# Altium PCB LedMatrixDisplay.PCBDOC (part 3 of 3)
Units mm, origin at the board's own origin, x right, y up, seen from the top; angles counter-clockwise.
Board outline 305.05 x 54.1 mm, 4 copper layers (Top Layer, POWER, GROUND, Bottom Layer); 103 components, 165 nets, 805 pads, 317 vias.
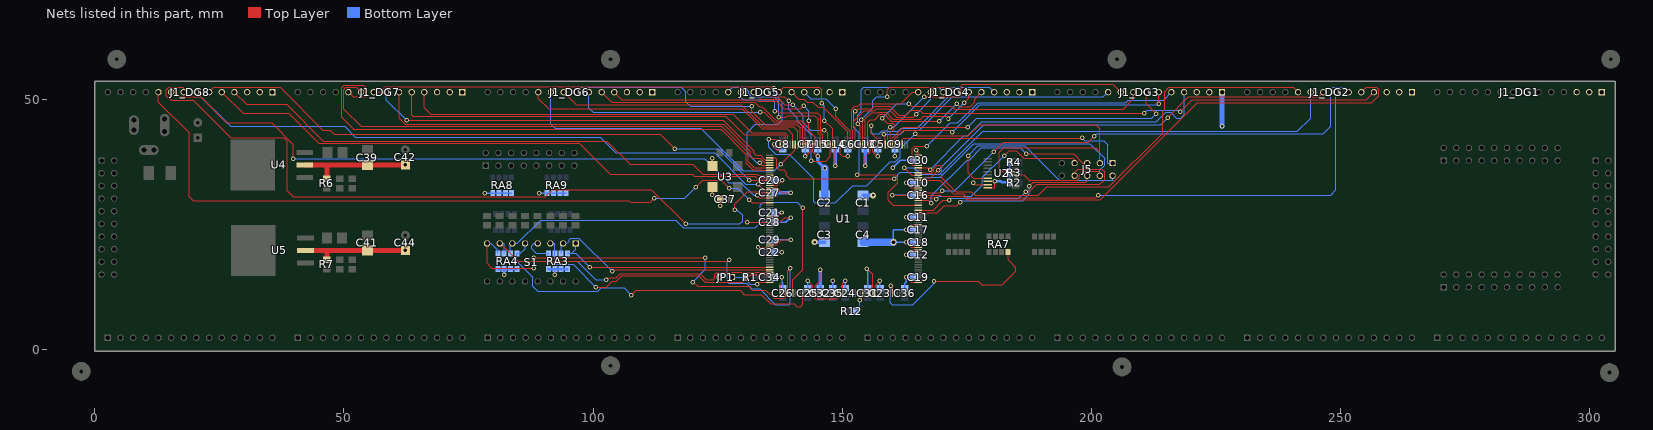
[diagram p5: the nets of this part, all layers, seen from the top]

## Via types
v1: diameter 0.9, hole 0.5, Top Layer to Bottom Layer, 307 vias
v2: diameter 1.2, hole 0.5, Top Layer to Bottom Layer, 9 vias
v3: diameter 1.27, hole 0.711, Top Layer to Bottom Layer, 1 vias

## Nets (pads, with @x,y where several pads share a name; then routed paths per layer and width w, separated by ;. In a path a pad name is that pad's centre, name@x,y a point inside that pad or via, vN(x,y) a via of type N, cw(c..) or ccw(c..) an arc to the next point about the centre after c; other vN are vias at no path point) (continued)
ROWB0: J1_DG2.4 U1.136 | length 141.5
  Top Layer w0.2: v1(152.629,47.752) 153.162,48.285 156.058,48.285 156.464,48.692 159.563,48.692 161.29,46.965 162.879,46.965 163.806,47.892 165.558,47.892 166.104,47.346 v1(210.566,47.346) ; v1(153.035,35.001) 160.757,35.001 161.163,34.595 161.163,33.35 159.258,31.445 159.258,29.863 160.198,28.923 U1.136@165.227,28.923 ; v1(217.805,47.6) 220.218,50.013 255.118,50.013 J1_DG2.4@256.667,51.562
  Bottom Layer w0.2: v1(152.629,47.752) 152.324,47.447 152.324,44.475 153.442,43.358 153.442,35.408 v1(153.035,35.001) ; v1(210.566,47.346) 211.201,47.981 217.424,47.981 v1(217.805,47.6)
ROWB1: J1_DG2.5 U1.140 | length 106.7
  Top Layer w0.2: U1.140@165.227,30.923 169.647,30.923 169.913,30.658 174.244,30.658 174.956,29.947 201.753,29.947 221.26,49.454 256.21,49.454 257.607,50.851 257.607,52.07 257.15,52.527 255.093,52.527 J1_DG2.5@254.127,51.562
ROWB2: J1_DG2.6 U1.141 | length 99.8
  Top Layer w0.2: U1.141@165.227,31.423 169.625,31.423 v1(170.028,31.826) ; v1(180.366,39.624) 182.245,41.504 199.365,41.504 v1(200.533,42.672)
  Bottom Layer w0.2: v1(170.028,31.826) 172.568,31.826 v1(180.366,39.624) ; v1(200.533,42.672) 201.041,43.18 246.482,43.18 248.031,44.729 248.031,52.07 248.463,52.502 250.648,52.502 J1_DG2.6@251.587,51.562
ROWB3: J1_DG2.7 U1.146 | length 105.5
  Top Layer w0.2: U1.146@165.227,33.923 169.545,33.923 172.252,31.217 174.27,31.217 175.083,30.404 200.838,30.404 v1(201.321,30.886)
  Bottom Layer w0.2: v1(201.321,30.886) 247.981,30.886 249.047,31.953 J1_DG2.7@249.047,51.562
ROWB4: J1_DG2.8 U1.147 | length 88.4
  Top Layer w0.2: U1.147@165.227,34.423 167.774,34.423 v1(169.241,35.89) ; v1(215.265,46.457) 219.431,50.622 245.568,50.622 J1_DG2.8@246.507,51.562
  Bottom Layer w0.2: v1(169.241,35.89) 178.385,45.034 213.843,45.034 v1(215.265,46.457)
ROWB5: J1_DG2.9 U1.148 | length 95.4
  Top Layer w0.2: v1(162.433,36.449) 163.959,34.923 U1.148@165.227,34.923
  Bottom Layer w0.2: v1(162.433,36.449) 164.338,36.449 165.735,35.052 169.545,35.052 178.181,43.688 241.3,43.688 243.967,46.355 J1_DG2.9@243.967,51.562
ROWB6: J1_DG2.10 U1.149 | length 94.9
  Top Layer w0.2: U1.149@165.227,35.423 166.675,35.423 166.843,35.255 167.92,35.255 168.377,35.712 168.377,36.22 169.012,36.855 169.545,36.855 170.003,36.398 170.003,34.366 172.746,31.623 175.895,31.623 176.683,30.836 189.307,30.836 191.059,32.588 203.505,32.588 214.249,43.332 214.249,47.752 214.681,48.184 214.681,51.664 215.545,52.527 240.462,52.527 J1_DG2.10@241.427,51.562
ROWC0: J1_DG4.4 U1.169 | length 35.1
  Top Layer w0.2: v1(155.829,44.856) 155.829,43.346 157.077,42.098 U1.169@157.077,41.073
  Bottom Layer w0.2: v1(155.829,44.856) 155.829,43.536 156.109,43.256 157.404,43.256 157.988,43.84 158.801,43.84 158.877,43.764 161.265,43.764 161.875,44.374 164.999,44.374 171.908,51.283 171.908,52.07 172.339,52.502 179.528,52.502 J1_DG4.4@180.467,51.562
ROWC1: J1_DG4.5 U1.173 | length 31.8
  Top Layer w0.2: U1.173@155.077,41.073 155.077,45.568 155.585,46.076 156.553,46.076 157.569,47.092 158.459,47.092 159.805,45.745 v1(169.469,45.745) ; v1(172.974,49.251) 173.584,48.641 175.641,48.641 176.53,49.53 176.53,50.165 J1_DG4.5@177.927,51.562
  Bottom Layer w0.2: v1(169.469,45.745) v1(172.974,49.251)
ROWC2: J1_DG4.6 U1.174 | length 30.3
  Top Layer w0.2: U1.174@154.577,41.073 154.577,45.306 154.661,45.39 154.661,46.203 155.931,47.473 157.252,47.473 157.277,47.498 158.801,47.498 160.147,46.152 165.735,46.152 166.269,46.685 170.866,46.685 v1(171.311,46.241) ; v1(174.473,49.403) 175.387,50.317 J1_DG4.6@175.387,51.562
  Bottom Layer w0.2: v1(171.311,46.241) v1(174.473,49.403)
ROWC3: J1_DG4.7 U1.175 | length 28.8
  Top Layer w0.2: v1(153.848,46.05) 154.077,45.821 U1.175@154.077,41.073 ; v1(159.055,50.622) 159.055,52.07 159.487,52.502 171.908,52.502 J1_DG4.7@172.847,51.562
  Bottom Layer w0.2: v1(153.848,46.05) 156.134,48.336 156.134,49.809 156.947,50.622 v1(159.055,50.622)
ROWC4: J1_DG4.8 U1.176 | length 28.5
  Top Layer w0.2: v1(153.086,45.237) 153.577,44.746 U1.176@153.577,41.073
  Bottom Layer w0.2: v1(153.086,45.237) 153.086,46.965 153.848,47.727 153.848,52.07 154.28,52.502 169.368,52.502 J1_DG4.8@170.307,51.562
ROWC5: J1_DG4.9 U1.178 | length 24.9
  Top Layer w0.2: U1.178@152.577,41.073 152.577,44.475 152.324,44.729 152.324,45.745 154.458,47.879 156.464,47.879 156.871,48.285 159.183,48.285 160.91,46.558 164.211,46.558 v1(164.796,47.142)
  Bottom Layer w0.2: v1(164.796,47.142) 167.767,50.114 J1_DG4.9@167.767,51.562
ROWC6: J1_DG4.10 U1.179 | length 21.9
  Top Layer w0.2: U1.179@152.077,41.073 152.077,43.935 151.867,44.145 151.867,48.082 152.477,48.692 153.112,48.692 153.645,49.225 161.748,49.225 164.084,51.562 J1_DG4.10@165.227,51.562
ROWD0: J1_DG6.4 U1.194 | length 48.3
  Top Layer w0.2: J1_DG6.4@104.267,51.562 105.791,50.038 132.792,50.038 133.122,49.708 136.83,49.708 138.303,48.235 141.682,48.235 v1(142.24,48.793) ; v1(143.256,45.847) 143.256,43.815 144.577,42.494 U1.194@144.577,41.073
  Bottom Layer w0.2: v1(142.24,48.793) 143.256,47.778 v1(143.256,45.847)
ROWD1: J1_DG6.5 U1.198 | length 47.6
  Top Layer w0.2: J1_DG6.5@101.727,51.562 103.709,49.581 132.461,49.581 133.376,48.666 133.935,48.666 136.793,45.808 141.898,45.808 142.577,45.129 U1.198@142.577,41.073
ROWD2: J1_DG6.6 U1.199 | length 51.3
  Top Layer w0.2: v1(133.579,47.498) 134.385,47.498 136.475,45.408 141.478,45.408 142.077,44.809 U1.199@142.077,41.073
  Bottom Layer w0.2: J1_DG6.6@99.187,51.562 99.187,48.362 100.051,47.498 v1(133.579,47.498)
ROWD3: J1_DG6.7 U1.200 | length 53.7
  Top Layer w0.2: v1(131.826,48.692) 131.826,47.727 134.545,45.008 140.996,45.008 140.996,45.002 141.577,44.42 U1.200@141.577,41.073
  Bottom Layer w0.2: J1_DG6.7@96.647,51.562 97.587,52.502 117.729,52.502 118.568,51.664 118.568,49.682 119.558,48.692 v1(131.826,48.692)
ROWD4: J1_DG6.8 U1.201 | length 52.9
  Top Layer w0.2: J1_DG6.8@94.107,51.562 96.622,49.047 129.693,49.047 134.132,44.608 140.177,44.608 141.077,43.708 U1.201@141.077,41.073
ROWD5: J1_DG6.9 U1.202 | length 62.1
  Top Layer w0.2: v1(137.668,37.084) 139.964,39.38 139.964,39.391 140.577,40.005 U1.202@140.577,41.073
  Bottom Layer w0.2: J1_DG6.9@91.567,51.562 91.567,45.161 92.406,44.323 121.565,44.323 130.099,35.789 136.373,35.789 v1(137.668,37.084)
ROWD6: J1_DG6.10 U1.203 | length 57.3
  Top Layer w0.2: J1_DG6.10@89.027,51.562 89.027,50.292 91.11,48.209 129.965,48.209 133.966,44.208 138.922,44.208 140.077,43.053 U1.203@140.077,41.073
ROWE0: J1_DG3.4 U1.151 | length 63.6
  Top Layer w0.2: U1.151@165.227,36.423 167.209,36.423 v1(167.615,36.017)
  Bottom Layer w0.2: v1(167.615,36.017) 174.371,42.774 175.21,42.774 178.029,45.593 212.979,45.593 214.884,47.498 215.9,47.498 217.043,46.355 217.932,46.355 218.567,46.99 J1_DG3.4@218.567,51.562
ROWE1: J1_DG3.5 U1.152 | length 61.1
  Top Layer w0.2: U1.152@165.227,36.923 164.084,36.923 164.084,40.284 164.516,40.716 v1(166.955,40.716)
  Bottom Layer w0.2: v1(166.955,40.716) 171.628,45.39 173.203,45.39 177.242,49.428 206.858,49.428 207.417,49.987 214.453,49.987 J1_DG3.5@216.027,51.562
ROWE2: J1_DG3.6 U1.162 | length 59.6
  Top Layer w0.2: U1.162@160.577,41.073 160.577,42.188 162.357,43.967 171.679,43.967 v1(172.111,43.536) ; v1(213.487,49.225) J1_DG3.6@213.487,51.562
  Bottom Layer w0.2: v1(172.111,43.536) 177.597,49.022 213.284,49.022 v1(213.487,49.225)
ROWE3: J1_DG3.7 U1.163 | length 61.3
  Top Layer w0.2: U1.163@160.077,41.073 160.077,42.297 162.281,44.501 v1(175.133,44.501) ; J1_DG3.7@210.947,51.562 210.947,49.251 v1(212.979,47.219)
  Bottom Layer w0.2: v1(175.133,44.501) 176.988,46.355 212.116,46.355 v1(212.979,47.219)
ROWE4: J1_DG3.8 U1.164 | length 61.6
  Top Layer w0.2: v1(158.014,46.33) 159.004,45.339 160.212,45.339 160.401,45.149 160.401,44.258 159.577,43.434 U1.164@159.577,41.073 ; v1(163.322,49.276) 163.906,48.692 171.983,48.692 172.517,48.158 206.325,48.158 208.407,50.241 J1_DG3.8@208.407,51.562
  Bottom Layer w0.2: v1(158.014,46.33) 160.96,49.276 v1(163.322,49.276)
ROWE5: J1_DG3.9 U1.165 | length 55.4
  Top Layer w0.2: U1.165@159.077,41.073 159.077,42.262 159.131,42.316 159.131,44.094 v1(159.589,44.552) ; v1(166.447,50.622) 173.584,50.622 173.889,50.927 173.889,52.883 174.194,53.188 204.242,53.188 J1_DG3.9@205.867,51.562
  Bottom Layer w0.2: v1(159.589,44.552) 160.376,44.552 v1(166.447,50.622)
ROWE6: J1_DG3.10 U1.166 | length 50.6
  Top Layer w0.2: v1(158.369,43.078) 158.577,42.87 U1.166@158.577,41.073
  Bottom Layer w0.2: v1(158.369,43.078) 161.621,43.078 162.51,43.967 165.405,43.967 172.035,50.597 202.362,50.597 J1_DG3.10@203.327,51.562
ROWF0: J1_DG8.4 U1.9 | length 114.3
  Top Layer w0.2: J1_DG8.4@28.067,51.562 30.506,49.124 38.532,49.124 45.924,41.732 102.769,41.732 107.442,37.059 120.041,37.059 121.997,35.103 132.995,35.103 133.174,34.923 U1.9@135.427,34.923
ROWF1: J1_DG8.5 U1.10 | length 117
  Top Layer w0.2: J1_DG8.5@25.527,51.562 29.795,47.295 38.964,47.295 44.984,41.275 97.206,41.275 103.429,35.052 119.965,35.052 120.32,34.696 132.512,34.696 132.785,34.423 U1.10@135.427,34.423
ROWF2: J1_DG8.6 U1.11 | length 120.5
  Top Layer w0.2: J1_DG8.6@22.987,51.562 23.927,52.502 37.211,52.502 45.746,43.967 47.168,43.967 48.057,43.078 113.488,43.078 v1(116.383,40.183) ; v1(131.344,33.934) 131.355,33.923 U1.11@135.427,33.923
  Bottom Layer w0.2: v1(116.383,40.183) 125.095,40.183 v1(131.344,33.934)
ROWF3: J1_DG8.7 U1.15 | length 123.1
  Top Layer w0.2: v1(133.147,33.096) 134.32,31.923 U1.15@135.427,31.923
  Bottom Layer w0.2: J1_DG8.7@20.447,51.562 27.305,44.704 50.165,44.704 52.324,42.545 101.429,42.545 104.579,39.395 124.384,39.395 130.683,33.096 v1(133.147,33.096)
ROWF4: J1_DG8.8 U1.16 | length 151.7
  Top Layer w0.2: J1_DG8.8@17.907,51.562 17.907,52.273 17.653,52.527 14.885,52.527 14.428,52.07 14.428,50.851 15.367,49.911 19.787,49.911 27.28,42.418 37.966,42.418 38.634,41.751 38.634,31.826 39.904,30.556 90.45,30.556 91.923,32.029 111.71,32.029 v1(118.618,25.121) ; v1(128.397,27.991) 128.397,29.083 130.912,31.598 133.633,31.598 133.808,31.423 U1.16@135.427,31.423
  Bottom Layer w0.2: v1(118.618,25.121) 129.464,25.121 129.998,25.654 129.998,26.873 128.88,27.991 v1(128.397,27.991)
ROWF5: J1_DG8.9 U1.18 | length 130.5
  Top Layer w0.2: J1_DG8.9@15.367,51.562 16.18,51.562 17.145,50.597 21.311,50.597 26.467,45.441 35.51,45.441 39.904,41.046 v1(39.904,38.227) ; v1(132.969,30.836) 133.382,30.423 U1.18@135.427,30.423
  Bottom Layer w0.2: v1(39.904,38.227) 122.428,38.227 127.229,33.426 129.667,33.426 132.258,30.836 v1(132.969,30.836)
ROWF6: J1_DG8.10 U1.20 | length 144.1
  Top Layer w0.2: J1_DG8.10@12.827,51.562 12.827,49.581 18.974,43.434 18.974,30.556 19.787,29.743 107.214,29.743 107.519,29.439 111.456,29.439 v1(112.294,30.277) ; v1(120.65,32.537) 121.971,33.858 125.68,33.858 v1(127.28,32.258) ; v1(131.318,29.997) 131.892,29.423 U1.20@135.427,29.423
  Bottom Layer w0.2: v1(112.294,30.277) 118.39,30.277 v1(120.65,32.537) ; v1(127.28,32.258) 129.058,32.258 v1(131.318,29.997)
ROWG0: J1_DG7.4 U1.205 | length 80.1
  Top Layer w0.2: J1_DG7.4@66.167,51.562 66.167,48.412 67.437,47.142 128.143,47.142 131.877,43.408 138.456,43.408 139.077,42.787 U1.205@139.077,41.073
ROWG1: J1_DG7.5 U1.206 | length 82.9
  Top Layer w0.2: J1_DG7.5@63.627,51.562 63.627,46.965 63.856,46.736 126.645,46.736 130.379,43.002 138.253,43.002 138.577,42.677 U1.206@138.577,41.073
ROWG2: J1_DG7.6 U1.4 | length 83.8
  Top Layer w0.2: J1_DG7.6@61.087,51.562 61.087,46.33 62.332,45.085 126.238,45.085 131.572,39.751 131.572,38.862 132.08,38.354 133.503,38.354 134.433,37.423 U1.4@135.427,37.423
ROWG3: J1_DG7.7 U1.3 | length 83.7
  Top Layer w0.2: v1(62.611,45.923) 126.111,45.923 132.207,39.827 132.207,39.37 132.715,38.862 133.604,38.862 134.366,38.1 134.353,38.088 134.518,37.923 U1.3@135.427,37.923
  Bottom Layer w0.2: J1_DG7.7@58.547,51.562 58.547,49.987 v1(62.611,45.923)
ROWG4: J1_DG7.8 U1.5 | length 105.6
  Top Layer w0.2: J1_DG7.8@56.007,51.562 57.176,51.562 58.268,52.654 135.89,52.654 v1(136.221,52.324) ; v1(133.401,37.389) 133.867,36.923 U1.5@135.427,36.923
  Bottom Layer w0.2: v1(133.401,37.389) 132.822,37.389 130.937,39.274 130.937,43.434 132.588,45.085 137.11,45.085 137.999,45.974 137.999,49.528 136.221,51.306 v1(136.221,52.324)
ROWG5: J1_DG7.9 U1.6 | length 99.3
  Top Layer w0.2: J1_DG7.9@53.467,51.562 52.528,52.502 50.419,52.502 49.988,52.07 49.988,48.158 53.467,44.679 125.857,44.679 131.153,39.382 131.153,37.63 132.36,36.423 U1.6@135.427,36.423
ROWG6: J1_DG7.10 U1.7 | length 108
  Top Layer w0.2: J1_DG7.10@50.927,51.562 51.867,50.622 54.179,50.622 54.407,50.851 54.407,52.476 53.925,52.959 50.064,52.959 49.581,52.476 49.581,46.558 52.045,44.094 125.68,44.094 130.753,39.021 130.753,37.268 132.004,36.017 133.782,36.017 133.876,35.923 U1.7@135.427,35.923
ROWH0: J1_DG5.4 U1.180 | length 16.1
  Top Layer w0.2: v1(148.667,48.285) 148.667,46.659 151.577,43.749 U1.180@151.577,41.073
  Bottom Layer w0.2: J1_DG5.4@142.367,51.562 143.714,50.216 146.736,50.216 v1(148.667,48.285)
ROWH1: J1_DG5.5 U1.181 | length 17.1
  Top Layer w0.2: J1_DG5.5@139.827,51.562 141.224,50.165 142.392,50.165 143.002,49.555 144.12,49.555 145.161,48.514 146.177,48.514 151.077,43.614 U1.181@151.077,41.073
ROWH2: J1_DG5.6 U1.187 | length 21
  Top Layer w0.2: J1_DG5.6@137.287,51.562 138.227,52.502 145.415,52.502 145.847,52.07 v1(145.847,49.352) ; v1(146.431,45.847) 148.077,44.201 U1.187@148.077,41.073
  Bottom Layer w0.2: v1(145.847,49.352) 146.431,48.768 v1(146.431,45.847)
ROWH3: J1_DG5.7 U1.188 | length 25.8
  Top Layer w0.2: J1_DG5.7@134.747,51.562 135.687,50.622 138.405,50.622 v1(139.218,49.809) ; v1(143.764,37.795) 143.714,37.744 146.663,37.744 147.577,38.659 U1.188@147.577,41.073
  Bottom Layer w0.2: v1(139.218,49.809) 139.218,48.133 140.996,46.355 140.996,45.821 143.764,43.053 v1(143.764,37.795)
ROWH4: J1_DG5.8 U1.189 | length 21.4
  Top Layer w0.2: J1_DG5.8@132.207,51.562 133.655,50.114 137.338,50.114 138.456,48.997 v1(140.031,48.997) ; v1(146.431,43.942) 147.077,43.296 U1.189@147.077,41.073
  Bottom Layer w0.2: v1(140.031,48.997) 142.19,46.838 142.19,45.389 143.637,43.942 v1(146.431,43.942)
ROWH5: J1_DG5.9 U1.191 | length 25.6
  Top Layer w0.2: v1(136.424,47.727) 137.058,47.727 137.363,47.422 144.983,47.422 145.677,46.728 145.677,43.426 146.077,43.026 U1.191@146.077,41.073
  Bottom Layer w0.2: J1_DG5.9@129.667,51.562 129.667,50.546 130.125,50.089 136.017,50.089 136.424,49.682 v1(136.424,47.727)
ROWH6: J1_DG5.10 U1.192 | length 28.8
  Top Layer w0.2: v1(137.237,46.558) 138.684,46.558 138.989,46.863 144.526,46.863 145.161,46.228 145.161,43.307 145.577,42.891 U1.192@145.577,41.073
  Bottom Layer w0.2: J1_DG5.10@127.127,51.562 128.067,52.502 130.429,52.502 131.268,51.664 131.268,51.105 131.75,50.622 136.339,50.622 137.237,49.725 v1(137.237,46.558)
SPARTAN_M0: JP1.1 R1.2 U1.52 | length 8.9
  Top Layer w0.2: v1(132.919,13.005) 132.943,13.005 133.362,13.423 U1.52@135.427,13.423
  Bottom Layer w0.2: JP1.1@127.889,14.478 128.575,14.478 128.63,14.423 R1.2@130.545,14.423 131.115,14.423 131.115,13.462 131.572,13.005 v1(132.919,13.005)
SW0: RA3.4 S1.1 U1.46 | length 44
  Top Layer w0.2: v1(99.314,16.434) 99.325,16.423 U1.46@135.427,16.423
  Bottom Layer w0.2: RA3.4@94.869,19.228 95.708,19.228 ; S1.1@96.52,21.209 96.52,20.041 95.708,19.228 ; v1(99.314,16.434) 96.52,19.228 95.708,19.228
SW1: RA3.3 S1.2 U1.47 | length 47.3
  Top Layer w0.2: v1(103.81,15.672) 104.062,15.923 U1.47@135.427,15.923
  Bottom Layer w0.2: RA3.3@93.599,19.228 93.599,21.209 S1.2@93.98,21.209 94.768,21.209 95.25,21.692 95.25,21.996 95.555,22.301 97.181,22.301 v1(103.81,15.672)
SW2: RA3.2 S1.3 U1.48 | length 50.7
  Top Layer w0.2: v1(102.616,13.945) 102.997,14.326 104.68,14.326 105.449,15.094 121.558,15.094 122.682,13.97 124.079,13.97 124.41,14.3 124.41,14.986 124.847,15.423 U1.48@135.427,15.423
  Bottom Layer w0.2: S1.3@91.44,21.209 92.126,21.209 92.329,21.006 RA3.2@92.329,19.228 92.329,18.059 92.736,17.653 96.8,17.653 100.508,13.945 v1(102.616,13.945)
SW3: RA3.1 S1.4 U1.49 | length 55.7
  Top Layer w0.2: v1(100.534,12.471) 102.693,12.471 103.836,13.614 104.648,13.614 105.728,14.694 121.196,14.694 122.479,13.411 130.125,13.411 131.637,14.923 U1.49@135.427,14.923
  Bottom Layer w0.2: S1.4@88.9,21.209 88.164,21.209 87.732,20.777 87.732,20.142 88.646,19.228 RA3.1@91.059,19.228 91.059,17.856 91.923,16.993 96.012,16.993 v1(100.534,12.471)
SW4: RA4.4 S1.5 U1.62 | length 70.7
  Top Layer w0.2: v1(107.696,10.846) 108.636,11.786 129.565,11.786 130.378,10.973 133.757,10.973 135.636,9.093 140.335,9.093 140.894,8.534 141.656,8.534 142.113,8.992 142.113,9.957 142.077,9.993 U1.62@142.077,11.273
  Bottom Layer w0.2: S1.5@86.36,21.209 86.36,20.168 85.421,19.228 RA4.4@84.709,19.228 84.709,17.653 87.91,14.453 87.91,12.649 88.9,11.659 100.965,11.659 101.625,12.319 106.223,12.319 v1(107.696,10.846)
SW5: RA4.3 S1.6 U1.58 | length 85.9
  Top Layer w0.2: U1.58@140.077,11.273 140.077,13.89 142.088,15.9 v1(142.088,28.397)
  Bottom Layer w0.2: RA4.3@83.439,19.228 83.439,21.209 S1.6@83.82,21.209 84.836,21.209 89.535,25.908 116.586,25.908 118.136,24.359 132.563,24.359 133.503,25.298 133.503,28.905 134.112,29.515 140.97,29.515 v1(142.088,28.397)
SW6: RA4.2 S1.7 U1.56 | length 82.1
  Top Layer w0.2: S1.7@81.28,21.209 81.814,21.209 81.814,20.828 85.014,17.628 127.026,17.628 v1(127.331,17.932) ; U1.56@139.077,11.273 139.077,15.735 v1(139.599,16.256)
  Bottom Layer w0.2: S1.7@81.28,21.209 81.966,21.209 82.169,21.006 RA4.2@82.169,19.228 ; v1(127.331,17.932) 126.95,17.551 126.95,13.462 127.178,13.233 130.709,13.233 131.827,12.115 133.427,12.115 136.601,8.941 139.345,8.941 139.599,9.195 v1(139.599,16.256)
SW7: RA4.1 S1.8 U1.55 | length 80.8
  Top Layer w0.2: S1.8@78.74,21.209 78.74,17.196 79.731,16.205 v1(88.138,16.205) ; v1(88.138,18.39) v1(122.555,18.39) ; v1(120.015,13.462) 120.142,13.462 121.006,12.598 131.42,12.598 131.522,12.497 131.522,12.243 131.953,11.811 134.697,11.811 136.322,10.185 138.349,10.185 138.577,10.414 U1.55@138.577,11.273
  Bottom Layer w0.2: S1.8@78.74,21.209 79.528,21.209 80.899,19.837 RA4.1@80.899,19.228 ; v1(88.138,16.205) v1(88.138,18.39) ; v1(120.015,13.462) 122.555,16.002 v1(122.555,18.39)
TCK_HARD: J5.3 U1.207 U2.6 | length 121.9
  Top Layer w0.2: v1(135.255,42.164) 138.077,42.164 U1.207@138.077,41.073 ; v1(164.643,43.18) 164.669,43.18 165.075,42.774 175.286,42.774 177.546,45.034 200.838,45.034 201.677,44.196 201.677,39.547 ; U2.6@184.758,35.627 182.102,35.627 181.509,36.22 181.509,39.472 182.423,40.386 200.838,40.386 201.677,39.547 ; J5.3@201.677,37.338 201.677,39.547
  Bottom Layer w0.2: v1(135.255,42.164) 135.236,42.145 135.236,40.532 136.652,39.116 139.319,39.116 144.272,34.163 144.272,29.591 144.526,29.337 148.616,29.337 152.07,32.791 154.89,32.791 159.665,37.567 160.628,37.567 161.646,38.584 161.646,40.183 v1(164.643,43.18)
TCK_SOFT: J5.7 U1.139 | length 37.9
  Top Layer w0.2: U1.139@165.227,30.423 168.58,30.423 v1(168.885,30.119) ; v1(182.449,38.811) 183.465,39.827 184.887,39.827 186.436,38.278 196.368,38.278 196.597,38.049 J5.7@196.597,37.338
  Bottom Layer w0.2: v1(168.885,30.119) 169.424,30.658 175.87,30.658 178.131,32.918 178.131,34.493 v1(182.449,38.811)
TDI_HARD: J5.1 U1.159 | length 47.6
  Top Layer w0.2: U1.159@162.077,41.073 162.077,42.113 162.331,42.367 198.044,42.367 v1(198.095,42.418)
  Bottom Layer w0.2: v1(198.095,42.418) 198.654,41.859 202.464,41.859 203.302,41.021 203.302,37.338 J5.1@204.217,37.338
TDI_SOFT: J5.5 U1.138 | length 40.9
  Top Layer w0.2: U1.138@165.227,29.923 167.283,29.923 v1(167.894,29.312) ; v1(186.919,39.167) 196.393,39.167 198.222,37.338 J5.5@199.137,37.338
  Bottom Layer w0.2: v1(167.894,29.312) 167.894,30.81 175.032,37.948 175.464,37.948 177.902,40.386 185.7,40.386 v1(186.919,39.167)
TDO_HARD: J5.2 U2.17 | length 41.4
  Top Layer w0.2: v1(175.235,38.811) 175.235,35.408 176.316,34.327 U2.17@179.208,34.327
  Bottom Layer w0.2: v1(175.235,38.811) 177.216,40.792 186.589,40.792 193.523,33.858 204.217,33.858 J5.2@204.217,34.798
TDO_SOFT: J5.6 U1.133 | length 38.5
  Top Layer w0.2: U1.133@165.227,27.423 169.091,27.423 170.471,28.804 173,28.804 v1(173.635,29.439) ; v1(187.554,32.69) 188.316,33.452 198.807,33.452 199.137,33.782 J5.6@199.137,34.798
  Bottom Layer w0.2: v1(173.635,29.439) 173.99,29.794 186.208,29.794 187.554,31.14 v1(187.554,32.69)
TMS_HARD: J5.4 U1.2 U2.5 | length 98.3
  Top Layer w0.2: U1.2@135.427,38.423 136.551,38.423 136.906,38.068 136.906,36.449 137.338,36.017 138.227,36.017 138.811,35.433 138.811,34.925 139.497,34.239 v1(160.401,34.239) ; U2.5@184.758,34.977 186.436,34.977 187.555,33.858 197.181,33.858 197.587,34.265 197.587,34.925 198.4,35.738 201.448,35.738 201.677,35.509 J5.4@201.677,34.798
  Bottom Layer w0.2: v1(160.401,34.239) 161.671,35.509 164.516,35.509 165.481,34.544 169.647,34.544 176.353,41.25 199.644,41.25 202.616,38.278 202.616,36.931 201.677,35.992 J5.4@201.677,34.798
TMS_SOFT: J5.8 U1.134 | length 48.7
  Top Layer w0.2: U1.134@165.227,27.923 168.233,27.923 170.155,29.845 v1(171.501,29.845) ; v1(186.792,31.598) 187.524,31.598 188.972,33.045 201.651,33.045 202.616,34.011 202.616,35.585 202.057,36.144 197.231,36.144 196.597,35.51 J5.8@196.597,34.798
  Bottom Layer w0.2: v1(171.501,29.845) 171.908,30.251 185.446,30.251 v1(186.792,31.598)
VCCINT: C2.1 C4.1 C13.2 C14.2 C15.2 C16.2 C17.2 C18.2 C27.1 C28.1 C29.1 C30.1 C31.1 C32.1 C41.1 C44.1 R7.1 U1.14 U1.28 U1.37 U1.67 U1.76 U1.90 U1.119 U1.128 U1.142 U1.172 U1.186 U1.195 U5.2 | length 142.9
  Top Layer w0.2: v1(130.963,25.451) 131.344,25.451 131.371,25.423 U1.28@135.427,25.423 137.437,25.423 138.43,26.416 v1(139.7,26.416) ; U1.37@135.427,20.923 136.84,20.923 137.84,21.923 v1(139.653,21.923) ; U1.14@135.427,32.423 136.84,32.423 137.84,31.423 v1(139.7,31.423) ; U1.195@144.077,41.073 144.077,39.66 v1(145.077,38.66) ; v1(145.577,15.967) 145.577,13.686 144.577,12.686 U1.67@144.577,11.273 144.577,10.16 149.077,10.16 U1.76@149.077,11.273 ; v1(148.577,36.83) U1.186@148.577,41.073 ; v1(154.577,36.83) 154.577,38.66 155.577,39.66 U1.172@155.577,41.073 ; v1(154.94,16.129) 156.077,14.992 U1.90@156.077,11.273 ; v1(160.02,30.861) 162.687,30.861 163.036,31.21 ; v1(162.814,21.423) 163.814,20.423 U1.119@165.227,20.423 ; v1(162.814,23.923) 163.814,24.923 U1.128@165.227,24.923 ; 162.814,30.923 163.1,31.21 ; 163.068,31.242 163.036,31.21 ; U1.142@165.227,31.923 163.814,31.923 163.1,31.21 ; 163.036,31.21 163.1,31.21
  Top Layer w1: U5.2@42.291,19.812 46.609,19.812 ; R7.1@46.609,17.968 46.609,19.812 ; C44.1@62.357,19.812 C41.1@54.737,19.812 46.609,19.812
  Bottom Layer w0.3: C29.1@136.377,21.923 v1(139.653,21.923) ; C28.1@136.377,25.423 138.684,25.423 139.677,26.416 v1(139.7,26.416) ; C27.1@136.377,31.423 137.84,31.423 ; v1(145.077,38.66) C15.2@145.077,40.123 ; C32.1@145.542,12.192 C32.1@145.577,12.223 ; v1(154.94,16.129) 155.077,15.992 C31.1@155.077,12.223 ; v1(160.02,30.861) 160.082,30.923 C16.2@164.277,30.923 ; v1(160.147,36.449) 161.621,37.923 C30.1@164.277,37.923 ; C18.2@164.277,21.423 v1(162.814,21.423) 160.314,21.423 v3(160.274,21.463) 160.274,23.923 v1(162.814,23.923) C17.2@164.277,23.923
  Bottom Layer w0.5: v1(139.653,21.923) v1@139.7,21.971 ; v1(139.7,26.416) v1@139.827,26.289
  Bottom Layer w0.7: C27.1@136.377,31.423 v1(139.7,31.423) ; v1(145.077,38.66) 145.077,37.676 v1(146.477,36.276) ; C32.1@145.577,12.223 v1(145.577,15.967) ; v1(148.577,36.83) C14.2@148.577,40.123 ; v1(154.577,36.83) C13.2@154.577,40.123
  Bottom Layer w1.5: C2.1@146.477,30.873 v1(146.477,36.276) ; C4.1@154.177,21.473 v3(160.274,21.463)
VCCO: C1.1 C3.1 C5.2 C6.2 C7.2 C8.2 C9.2 C10.2 C11.2 C12.2 C19.1 C20.1 C21.1 C22.1 C23.1 C24.1 C25.1 C26.1 C34.2 C35.2 C36.2 C37.1 C39.1 C42.1 J1_DG1.1 J1_DG1.2 J1_DG1.3 J1_DG2.1 J1_DG2.2 J1_DG2.3 J1_DG3.1 J1_DG3.2 J1_DG3.3 J1_DG4.1 J1_DG4.2 J1_DG4.3 J1_DG5.1 J1_DG5.2 J1_DG5.3 J1_DG6.1 J1_DG6.2 J1_DG6.3 J1_DG7.1 J1_DG7.2 J1_DG7.3 J1_DG8.1 J1_DG8.2 J1_DG8.3 JP1.2 R2.1 R3.1 R4.1 R6.1 RA3.5 RA3.6 RA3.7 RA3.8 RA4.5 RA4.6 RA4.7 RA4.8 RA8.5 RA8.6 RA8.7 RA8.8 RA9.5 RA9.6 RA9.7 RA9.8 U1.13 U1.26 U1.38 U1.53 U1.66 U1.78 U1.91 U1.105 U1.118 U1.130 U1.143 U1.156 U1.171 U1.184 U1.196 U1.208 U2.18 U2.19 U2.20 U3.1 U3.4 U4.2 | length 148.2
  Top Layer w0.2: v1(133.096,20.423) U1.38@135.427,20.423 ; U1.26@135.427,26.423 136.84,26.423 v1(137.84,27.423) ; U1.13@135.427,32.923 136.937,32.923 v1(137.922,33.909) ; v1(136.398,41.148) 136.398,40.513 136.906,40.005 137.577,40.005 U1.208@137.577,41.073 ; U1.53@137.577,11.273 137.577,13.117 137.84,13.38 v1(137.84,14.423) ; v1(142.577,38.66) 143.577,39.66 U1.196@143.577,41.073 ; v1(143.077,13.686) 144.077,12.686 U1.66@144.077,11.273 ; U1.184@149.577,41.073 149.577,39.145 150.062,38.66 v1(151.077,38.66) ; U1.78@150.077,11.273 150.077,13.186 v1(150.577,13.686) ; U1.171@156.077,41.073 156.077,39.66 v1(157.077,38.66) ; U1.91@156.577,11.273 156.577,12.728 v1(157.567,13.718) ; v1(162.814,14.423) 163.814,13.423 U1.105@165.227,13.423 ; v1(162.814,18.923) 163.814,19.923 U1.118@165.227,19.923 ; v1(162.814,26.423) 163.314,25.923 U1.130@165.227,25.923 ; v1(162.814,33.423) 163.814,32.423 U1.143@165.227,32.423 ; v1(164.846,39.878) 165.227,39.497 U1.156@165.227,38.923 ; v1(176.276,33.426) 176.676,33.027 U2.19@179.208,33.027 ; U2.20@179.208,32.377 180.61,32.377 v1(180.61,33.677) U2.18@179.208,33.677
  Top Layer w0.3: v1(123.952,30.954) U3.1@123.952,32.531 ; U3.4@123.952,36.731 v1(123.952,38.308) ; v1(125.542,28.772) C37.1@125.542,30.099
  Top Layer w0.5: R6.1@46.609,34.224 R6.1@46.609,34.417 ; C42.1@62.206,36.957 C42.1@62.23,36.981
  Top Layer w1: U4.2@42.164,36.957 46.609,36.957 ; R6.1@46.609,34.417 46.609,36.957 ; C42.1@62.357,36.957 62.206,36.957 C39.1@54.737,36.957 46.609,36.957
  Bottom Layer w0.254: v1(92.329,14.901) RA3.7@92.329,16.078
  Bottom Layer w0.3: v1(78.283,31.318) RA8.8@79.883,31.318 RA8.7@81.153,31.318 RA8.6@82.423,31.318 RA8.5@83.693,31.318 ; v1(89.205,31.318) RA9.8@90.805,31.318 RA9.7@92.075,31.318 RA9.6@93.345,31.318 RA9.5@94.615,31.318 ; C34.2@136.377,14.423 v1(137.84,14.423) 137.84,13.507 138.077,13.27 C26.1@138.077,12.223 ; C22.1@136.377,19.423 v1(137.84,19.423) ; C21.1@136.377,27.423 v1(137.84,27.423) ; C20.1@136.377,33.923 136.459,33.909 v1(137.922,33.909) ; v1(142.577,38.66) C7.2@142.577,40.123 ; C25.1@143.077,12.223 v1(143.077,13.686) ; C35.2@148.077,12.223 v1(148.077,13.686) ; C24.1@150.577,12.223 v1(150.577,13.686) ; v1(151.077,38.66) C6.2@151.077,40.123 ; v1(157.077,38.66) C5.2@157.077,40.123 ; v1(157.567,13.718) 157.567,12.255 C23.1@157.577,12.223 ; v1(160.577,38.66) C9.2@160.577,40.123 ; C36.2@162.577,12.223 162.577,13.225 162.814,13.462 v1(162.814,14.423) C19.1@164.277,14.423 ; v1(162.814,18.923) C12.2@164.277,18.923 ; v1(162.814,26.423) C11.2@164.277,26.423 ; v1(162.814,33.423) C10.2@164.277,33.423 ; R2.1@183.581,33.401 R3.1@183.581,35.433 R4.1@183.581,37.465
  Bottom Layer w0.5: RA4.8@80.899,16.078 RA4.7@82.169,16.078 ; v1(82.169,14.901) RA4.7@82.169,16.078 ; RA4.5@84.709,16.078 RA4.6@83.439,16.078 RA4.7@82.169,16.078 ; RA3.8@91.059,16.078 RA3.7@92.329,16.078 RA3.6@93.599,16.078 RA3.5@94.869,16.078 ; v1(136.398,41.148) 136.398,40.64 136.915,40.123 C8.2@138.077,40.123 ; v1(180.61,33.677) 181.842,33.677 181.991,33.528 183.454,33.528 R2.1@183.581,33.401
  Bottom Layer w0.7: v2(144.444,21.473) C3.1@146.477,21.473 ; C1.1@154.177,30.873 v2(156.21,30.873)
  Bottom Layer w1: v1(226.187,44.704) J1_DG3.1@226.187,51.562
WR: RA7.8 U1.98 | length 38.7
  Top Layer w0.2: v1(159.741,12.776) 160.077,12.44 U1.98@160.077,11.273 ; v1(168.402,13.614) 177.267,13.614 177.978,12.903 182.118,12.903 184.811,15.596 184.811,16.383 183.262,17.932 RA7.8@183.262,19.507
  Bottom Layer w0.2: v1(159.741,12.776) 159.639,12.675 159.639,9.271 160.02,8.89 164.186,8.89 168.402,13.106 v1(168.402,13.614)
WR_REG: R12.1 U1.86 | length 4.5
  Top Layer w0.2: v1(153.493,9.83) 154.077,10.415 U1.86@154.077,11.273
  Bottom Layer w0.2: R12.1@152.842,7.62 153.493,7.62 v1(153.493,9.83)
pads on no net: J2_DG1.6 J2_DG2.6 J2_DG3.6 J2_DG4.6 J2_DG5.6 J2_DG6.6 J2_DG7.6 J2_DG8.6 U1.64 U1.69 U1.70 U1.71 U1.73 U1.74 U1.75 U1.77 U1.80 U1.81 U1.82 U1.83 U1.84 U1.87 U1.88 U1.89 U1.93 U1.94 U1.95 U1.182 U2.2 U2.9 U2.12 U2.13 U2.14 U2.15 U2.16 U4.4 U5.4
copper on no net: | length 717.3
  Bottom Layer w0.254: 0.127,-0.254 304.927,-0.254 304.927,53.594 0.127,53.594 0.127,-0.254

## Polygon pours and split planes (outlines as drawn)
6V on POWER (split plane): 28.93,50.038 28.935,49.998 28.95,49.961 28.975,49.929 29.006,49.905 29.044,49.89 29.083,49.884 37.211,49.884 37.251,49.89 37.288,49.905 37.32,49.929 37.344,49.961 37.36,49.998 37.365,50.038 37.365,52.424 67.03,52.424 67.03,50.038 67.035,49.998 67.05,49.961 67.075,49.929 67.106,49.905 67.144,49.89 67.183,49.884 75.311,49.884 75.351,49.89 75.388,49.905 75.42,49.929 75.444,49.961 75.46,49.998 75.465,50.038 75.465,52.424 105.13,52.424 105.13,50.038 105.135,49.998 105.15,49.961 105.175,49.929 105.206,49.905 105.244,49.89 105.283,49.884 113.411,49.884 113.451,49.89 113.488,49.905 113.52,49.929 113.544,49.961 113.56,49.998 113.565,50.038 113.565,52.424 143.23,52.424 143.23,50.038 143.235,49.998 143.25,49.961 143.275,49.929 143.306,49.905 143.344,49.89 143.383,49.884 151.511,49.884 151.551,49.89 151.588,49.905 151.62,49.929 151.644,49.961 151.66,49.998 151.665,50.038 151.665,52.424 181.33,52.424 181.33,50.038 181.335,49.998 181.35,49.961 181.375,49.929 181.406,49.905 181.444,49.89 181.483,49.884 189.611,49.884 189.651,49.89 189.688,49.905 189.72,49.929 189.744,49.961 189.76,49.998 189.765,50.038 189.765,52.424 219.43,52.424 219.43,50.038 219.435,49.998 219.45,49.961 219.475,49.929 219.506,49.905 219.544,49.89 219.583,49.884 227.711,49.884 227.751,49.89 227.788,49.905 227.82,49.929 227.844,49.961 227.86,49.998 227.865,50.038 227.865,52.424 257.53,52.424 257.53,50.038 257.535,49.998 257.55,49.961 257.575,49.929 257.606,49.905 257.644,49.89 257.683,49.884 265.557,49.884 265.597,49.89 265.634,49.905 265.666,49.929 265.69,49.961 265.706,49.998 265.711,50.038 265.711,52.424 295.63,52.424 295.63,49.784 295.635,49.744 295.65,49.707 295.675,49.675 295.706,49.651 295.744,49.636 295.783,49.63 304.544,49.63 304.544,0.129 0.51,0.129 0.51,53.211 28.93,53.211
VCCO on POWER (split plane): 254.1,9.298 50.954,9.298 50.954,45.566 254.101,45.566
VCCINT on POWER (split plane): 161.034,36.776 161.034,17.199 159.077,15.242 140.389,15.242 139.919,15.713 139.877,15.741 139.827,15.75 137.414,15.75 137.364,15.741 137.322,15.713 136.852,15.242 129.721,15.242 128.743,16.22 128.235,16.729 128.193,16.757 128.143,16.766 61.776,16.766 60.479,18.063 60.479,21.436 69.44,21.436 70.901,19.974 70.943,19.946 70.993,19.937 130.883,19.937 132.566,18.254 132.567,18.248 132.582,18.211 132.607,18.179 132.638,18.155 132.676,18.14 132.715,18.134 138.811,18.134 138.851,18.14 138.888,18.155 138.92,18.179 138.944,18.211 138.959,18.248 138.965,18.288 138.959,18.328 138.944,18.365 138.94,18.37 138.94,32.764 140.789,32.764 143.127,30.426 143.127,30.099 143.127,20.828 143.136,20.778 143.164,20.736 144.434,19.466 144.476,19.438 144.526,19.429 156.337,19.429 156.387,19.438 156.429,19.466 157.572,20.609 157.6,20.651 157.609,20.701 157.609,32.512 157.6,32.562 157.572,32.604 155.921,34.255 155.879,34.283 155.829,34.292 146.739,34.292 145.417,35.614 145.417,37.336 160.474,37.336
VCCO on POWER (split plane): 304.544,49.938 295.937,49.938 295.937,52.578 295.932,52.618 295.916,52.655 295.892,52.687 295.86,52.711 295.823,52.726 295.783,52.732 265.557,52.732 265.518,52.726 265.48,52.711 265.449,52.687 265.424,52.655 265.409,52.618 265.404,52.578 265.404,50.192 257.837,50.192 257.837,52.578 257.832,52.618 257.816,52.655 257.792,52.687 257.76,52.711 257.723,52.726 257.683,52.732 227.711,52.732 227.672,52.726 227.634,52.711 227.603,52.687 227.578,52.655 227.563,52.618 227.558,52.578 227.558,50.192 219.737,50.192 219.737,52.578 219.732,52.618 219.716,52.655 219.692,52.687 219.66,52.711 219.623,52.726 219.583,52.732 189.611,52.732 189.572,52.726 189.534,52.711 189.503,52.687 189.478,52.655 189.463,52.618 189.458,52.578 189.458,50.192 181.637,50.192 181.637,52.578 181.632,52.618 181.616,52.655 181.592,52.687 181.56,52.711 181.523,52.726 181.483,52.732 151.511,52.732 151.472,52.726 151.434,52.711 151.403,52.687 151.378,52.655 151.363,52.618 151.358,52.578 151.358,50.192 143.537,50.192 143.537,52.578 143.532,52.618 143.516,52.655 143.492,52.687 143.46,52.711 143.423,52.726 143.383,52.732 113.411,52.732 113.372,52.726 113.334,52.711 113.303,52.687 113.278,52.655 113.263,52.618 113.258,52.578 113.258,50.192 105.437,50.192 105.437,52.578 105.432,52.618 105.416,52.655 105.392,52.687 105.36,52.711 105.323,52.726 105.283,52.732 75.311,52.732 75.272,52.726 75.234,52.711 75.203,52.687 75.178,52.655 75.163,52.618 75.158,52.578 75.158,50.192 67.337,50.192 67.337,52.578 67.332,52.618 67.316,52.655 67.292,52.687 67.26,52.711 67.223,52.726 67.183,52.732 37.211,52.732 37.172,52.726 37.134,52.711 37.103,52.687 37.078,52.655 37.063,52.618 37.058,52.578 37.058,50.192 29.237,50.192 29.237,53.211 304.544,53.211
GND on GROUND (split plane): 304.544,0.129 0.51,0.129 0.51,53.211 304.544,53.211

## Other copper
Top Layer:
  text "1" at 136.017,39.497 h1 r90
POWER (plane layer: these items are gaps in the copper):
  lines w0.254: 60.325,18.034 61.722,16.637 128.143,16.637 128.651,16.129 129.667,15.113 136.906,15.113 137.414,15.621 139.827,15.621 140.335,15.113 144.272,15.113 ; 69.215,21.59 69.469,21.59 70.993,20.066 130.937,20.066 132.715,18.288 133.477,18.288 ; 138.811,18.288 138.811,32.893 140.843,32.893 143.256,30.48 143.256,30.099 143.256,20.828 144.526,19.558 156.337,19.558 157.48,20.701 157.48,32.512 155.829,34.163 146.685,34.163 145.288,35.56 145.288,37.465 160.528,37.465 161.163,36.83 161.163,17.145 159.131,15.113 143.764,15.113
  lines w0.305: 29.083,53.721 29.083,50.038 37.211,50.038 37.211,52.578 67.183,52.578 ; 60.325,18.034 60.325,21.59 ; 60.579,21.59 60.325,21.59 ; 69.469,21.59 60.325,21.59 ; 132.715,18.288 138.811,18.288 ; 305.055,49.784 295.783,49.784 295.783,52.578 265.557,52.578 265.557,50.038 257.683,50.038 257.683,52.578 227.711,52.578 227.711,50.038 219.583,50.038 219.583,52.578 189.611,52.578 189.611,50.038 181.483,50.038 181.483,52.578 151.511,52.578 151.511,50.038 143.383,50.038 143.383,52.578 113.411,52.578 113.411,50.038 105.283,50.038 105.283,52.578 75.311,52.578 75.311,50.038 67.183,50.038 ; 67.183,50.038 67.183,52.578 ; 67.183,50.038 67.183,52.578 ; 50.8,9.144 254.254,9.144 254.255,45.72 50.8,45.72 50.8,9.144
